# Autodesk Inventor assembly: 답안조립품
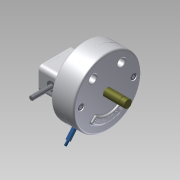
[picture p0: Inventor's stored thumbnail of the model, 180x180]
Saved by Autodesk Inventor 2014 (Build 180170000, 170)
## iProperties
Created: 2015-04
Part Number: 답안조립품
Document SubType Name: Assembly
Designer: Administrator
Author: Administrator
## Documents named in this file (15)
- C:\Documents and Settings\Administrator\바탕 화면\350406V1021\답안조립품.iam
- C:\Documents and Settings\Administrator\바탕 화면\350406V1021\본체.ipt
- C:\Documents and Settings\Administrator\바탕 화면\350406V1021\커버.ipt
- C:\Documents and Settings\Administrator\바탕 화면\350406V1021\베어링62_22.ipt
- C:\Documents and Settings\Administrator\바탕 화면\350406V1021\커버2.ipt
- C:\Documents and Settings\Administrator\바탕 화면\350406V1021\축.ipt
- C:\Documents and Settings\Administrator\바탕 화면\350406V1021\멈춤링.ipt
- C:\Documents and Settings\Administrator\바탕 화면\350406V1021\슬라이더2.ipt
- C:\Documents and Settings\Administrator\바탕 화면\350406V1021\슬라이더.ipt
- C:\Documents and Settings\Administrator\바탕 화면\350406V1021\M 5 x 12.ipt
- C:\Documents and Settings\Administrator\바탕 화면\350406V1021\M 10 x 35.ipt
- C:\Documents and Settings\Administrator\바탕 화면\350406V1021\평행핀.ipt
- C:\Documents and Settings\Administrator\바탕 화면\350406V1021\부시.ipt
- C:\Documents and Settings\Administrator\바탕 화면\350406V1021\슬라이더3.ipt
- C:\Documents and Settings\Administrator\바탕 화면\350406V1021\스프링 - [가변].ipt
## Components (5 placed, 3 different names)
1. M 5 x 12:1
2. M 5 x 12:2
3. M 10 x 35:1
4. M 10 x 35:2
5. KS B 1320 B B 5 x  20:1 — 플러쉬:2
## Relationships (1: Flush 1)
- 플러쉬:2 [Flush]: KS B 1320 B B 5 x  20:1
